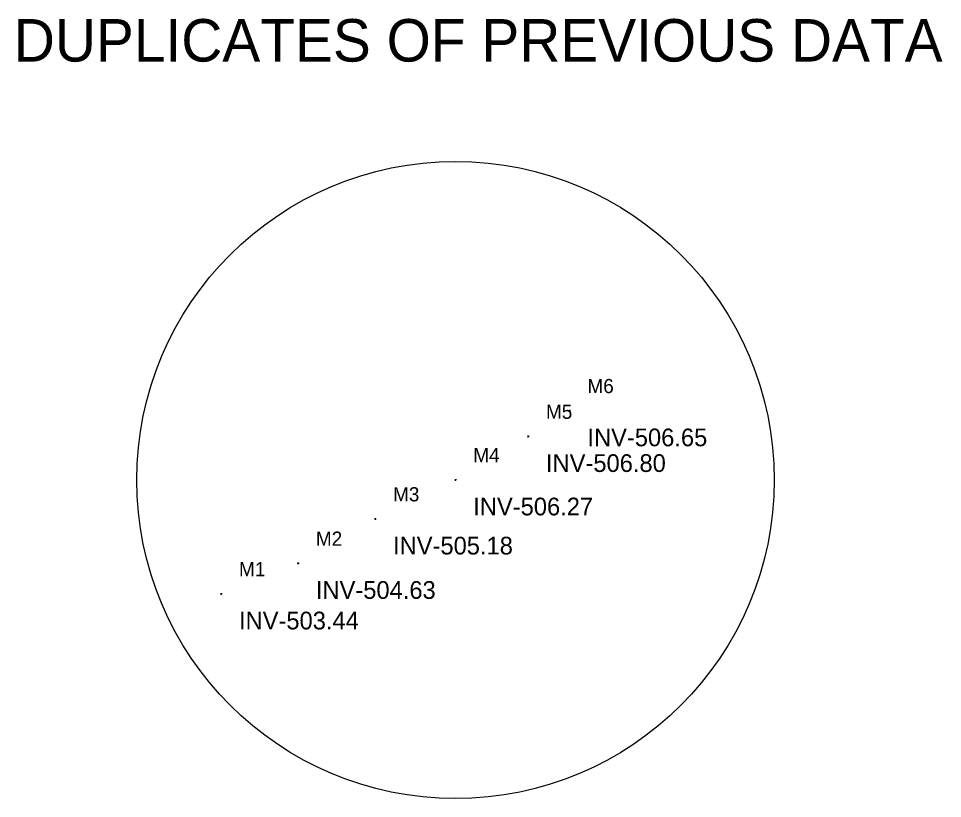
# Model space of a CAD drawing. Extents: x 1728037 to 1741597, y 649934 to 653706.
# Drawn here: x 1741336.1 to 1741596.9, y 650419.5 to 650639.7 of the extents above; entities that cross this region are included whole.
import ezdxf

# ---------------------------------------------------------------- set-up
doc = ezdxf.new("R2010")
doc.units = 0
for name, color, linetype in [('SURVEY - CENTERLINE - Preliminary', 7, 'Continuous'), ('SURVEY - DRAINAGE - Storm Sewer - Points - Elevations', 7, 'Continuous'), ('SURVEY - DRAINAGE - Storm Sewer - Points - Locators', 7, 'Continuous'), ('SURVEY - DRAINAGE - Storm Sewer - Points - Numbers', 7, 'Continuous')]:
    doc.layers.add(name, color=color, linetype=linetype)

msp = doc.modelspace()

# ---------------------------------------------------------------- linework, layer by layer
at = {"layer": 'SURVEY - CENTERLINE - Preliminary'}
msp.add_circle((1741459.44, 650509.43), 89.95, dxfattribs=at)
at = {"layer": 'SURVEY - DRAINAGE - Storm Sewer - Points - Locators'}
for p, q in [((1741491.91, 650528.94), (1741491.41, 650528.94)), ((1741491.66, 650528.69), (1741491.66, 650529.19)), ((1741491.66, 650528.94), (1741491.66, 650528.94)), ((1741491.66, 650528.94), (1741491.66, 650528.94)), ((1741480.21, 650521.69), (1741479.71, 650521.69)), ((1741479.96, 650521.44), (1741479.96, 650521.94)), ((1741479.96, 650521.69), (1741479.96, 650521.69)), ((1741479.96, 650521.69), (1741479.96, 650521.69)), ((1741459.69, 650509.43), (1741459.19, 650509.43)), ((1741459.44, 650509.18), (1741459.44, 650509.68)), ((1741459.44, 650509.43), (1741459.44, 650509.43)), ((1741459.44, 650509.43), (1741459.44, 650509.43)), ((1741437.05, 650498.39), (1741436.55, 650498.39)), ((1741436.8, 650498.14), (1741436.8, 650498.64)), ((1741436.8, 650498.39), (1741436.8, 650498.39)), ((1741436.8, 650498.39), (1741436.8, 650498.39)), ((1741415.02, 650485.61), (1741415.02, 650486.11)), ((1741415.27, 650485.86), (1741414.77, 650485.86)), ((1741415.02, 650485.86), (1741415.02, 650485.86)), ((1741415.02, 650485.86), (1741415.02, 650485.86)), ((1741393.57, 650477.23), (1741393.07, 650477.23)), ((1741393.32, 650476.98), (1741393.32, 650477.48)), ((1741393.32, 650477.23), (1741393.32, 650477.23)), ((1741393.32, 650477.23), (1741393.32, 650477.23))]:
    msp.add_line(p, q, dxfattribs=at)

# ---------------------------------------------------------------- texts
at = {"layer": 'SURVEY - CENTERLINE - Preliminary'}
msp.add_text('DUPLICATES OF PREVIOUS DATA', height=12, dxfattribs=at).set_placement((1741334.76, 650627.56))
at = {"layer": 'SURVEY - DRAINAGE - Storm Sewer - Points - Elevations'}
for s, p in [('INV-506.65', (1741496.66, 650518.94)), ('INV-506.80', (1741484.96, 650511.69)), ('INV-506.27', (1741464.44, 650499.43)), ('INV-505.18', (1741441.8, 650488.39)), ('INV-504.63', (1741420.02, 650475.86)), ('INV-503.44', (1741398.32, 650467.23))]:
    msp.add_text(s, height=5, dxfattribs=at).set_placement(p)
at = {"layer": 'SURVEY - DRAINAGE - Storm Sewer - Points - Numbers'}
for s, p in [('M6', (1741496.66, 650533.94)), ('M5', (1741484.96, 650526.69)), ('M4', (1741464.44, 650514.43)), ('M3', (1741441.8, 650503.39)), ('M2', (1741420.02, 650490.86)), ('M1', (1741398.32, 650482.23))]:
    msp.add_text(s, height=4, dxfattribs=at).set_placement(p)

doc.saveas('drawing.dxf')
